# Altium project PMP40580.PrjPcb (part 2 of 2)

## Sheet PMP40580_LLC.SchDoc
size 431 x 279 mm; Date: Not shown in title block; ApprovedBy: Not shown in title block; CheckedBy: Not shown in title block; Author: Not shown in title block; CompanyName: Not shown in title block; DrawnBy: Oliver Pan; Engineer: Not shown in title block; Organization: Not shown in title block; Address1: Not shown in title block; Address2: Not shown in title block; Address3: Not shown in title block; Address4: Not shown in title block; DocumentNumber: 1; Revision: Use project parameter SCH_Rev; SheetNumber: 3; SheetTotal: 3; PageSetup: Record=PageOptions¦CenterHorizontal=True¦CenterVertical=True¦PrintScale=0.64¦XCorrection=1.00¦YCorrection=1.00¦PrintKind=1¦BorderSize=5000000¦LeftOffset=0¦BottomOffset=0¦Orientation=2¦PaperLength=1000¦PaperWidth=1000¦Scale=100¦PaperSource=15¦PrintQuality=-3¦MediaType=1¦DitherType=10¦PrintScaleMode=1¦PaperKind=Letter¦PaperIndex=1
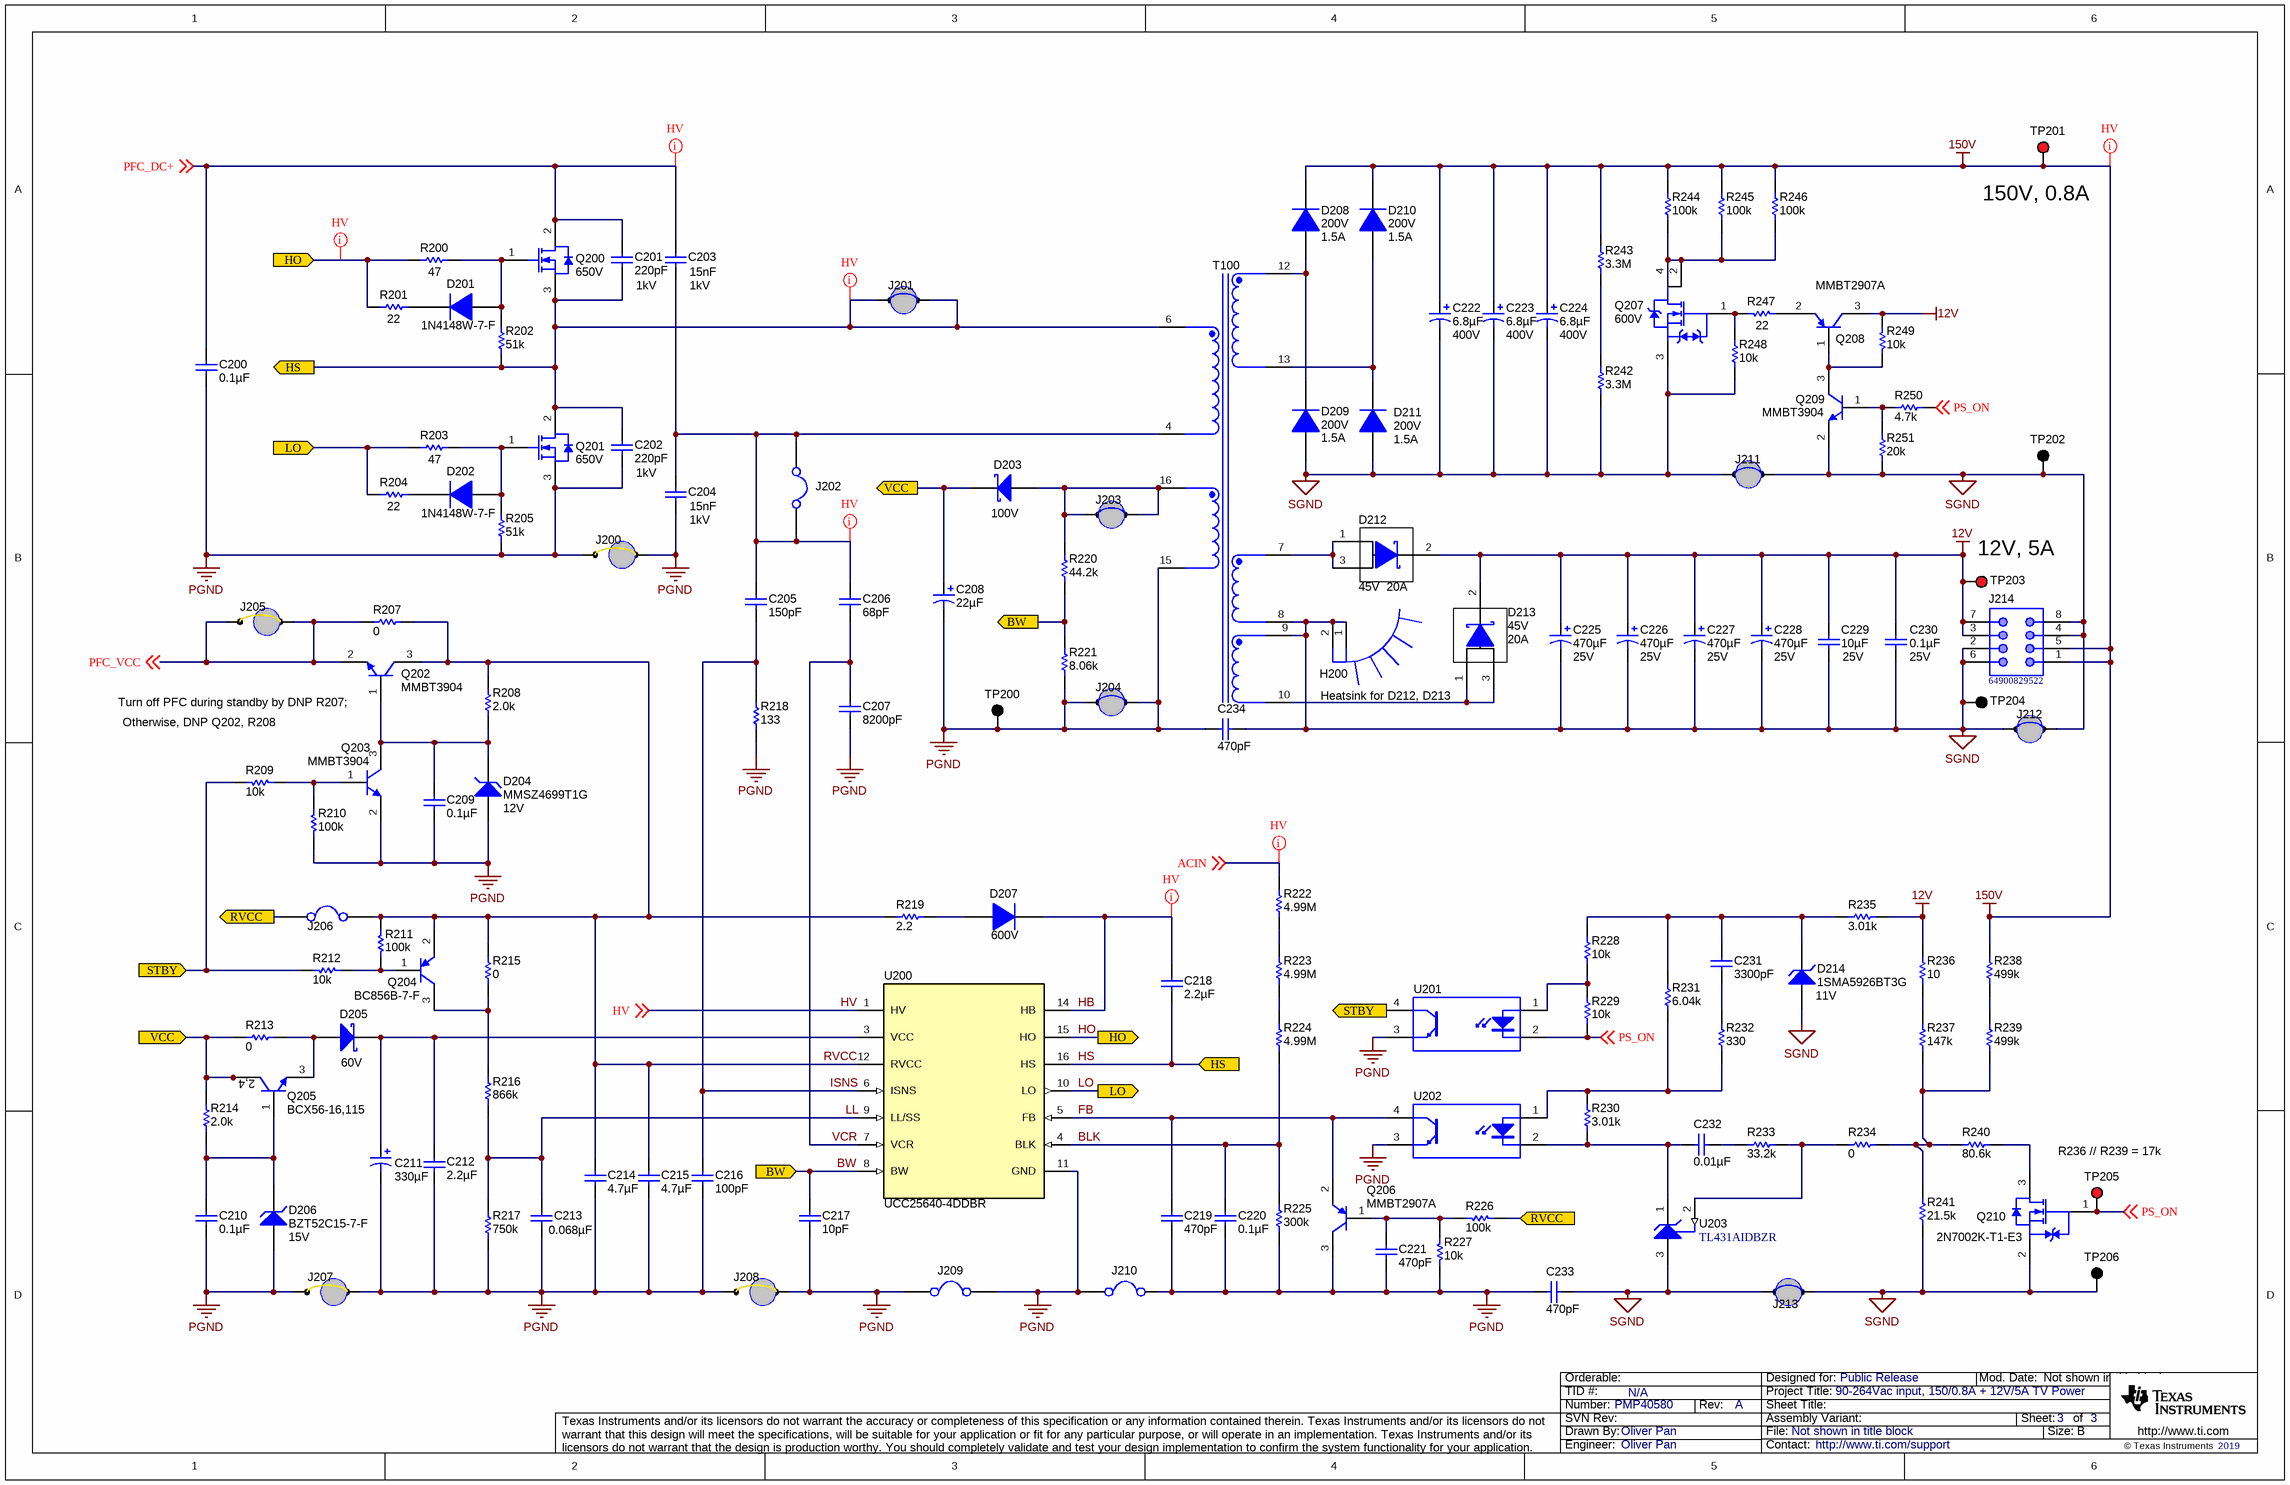
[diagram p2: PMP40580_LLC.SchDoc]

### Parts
C200  ValueDisplayed: 0.1µF  [1210_280]  (hidden comment: C1210C104KBRAC7800)
C201  ValueDisplayed: 220pF  Value2: 1kV  [CC45_850x500x1250]  (hidden comment: CC45SL3AD221JYNNA)
C202  ValueDisplayed: 220pF  Value2: 1kV  [CC45_850x500x1250]  (hidden comment: CC45SL3AD221JYNNA)
C203  value 15nF  Voltage Rating (DC): 1kV  [B32652_1800x700x1250]  (hidden comment: B32642B0153J)
C204  value 15nF  Voltage Rating (DC): 1kV  [B32652_1800x700x1250]  (hidden comment: B32642B0153J)
C205  ValueDisplayed: 150pF  [1206]  (hidden comment: GRM31A5C2J151JW01D)
C206  ValueDisplayed: 68pF  [1206]  (hidden comment: 12067A680JAT2A)
C207  ValueDisplayed: 8200pF  [1206]  (hidden comment: GRM3195C1H822JA01D)
C208  ValueDisplayed: 22µF  [Chemi-Con_500x1100]  (hidden comment: EKZE500ELL220ME11D)
C209  ValueDisplayed: 0.1µF  [0805_HV]  (hidden comment: 08055C104JAT2A)
C210  ValueDisplayed: 0.1µF  [0805_HV]  (hidden comment: 08055C104JAT2A)
C211  ValueDisplayed: 330µF  [VR_1000x1250]  (hidden comment: UVR1V331MPD)
C212  ValueDisplayed: 2.2µF  [1206_180]  (hidden comment: C3216X7S2A225K160AB)
C213  ValueDisplayed: 0.068µF  [0805_HV]  (hidden comment: C0805C683K1RACTU)
C214  ValueDisplayed: 4.7µF  [0805_HV]  (hidden comment: GRM21BR71E475KA73L)
C215  ValueDisplayed: 4.7µF  [0805_HV]  (hidden comment: GRM21BR71E475KA73L)
C216  ValueDisplayed: 100pF  [0805_HV]  (hidden comment: GRM2165C1H101JA01D)
C217  ValueDisplayed: 10pF  [0805_HV]  (hidden comment: C0805C100J5GACTU)
C218  ValueDisplayed: 2.2µF  [0805_HV]  (hidden comment: GRM219R71C225KE15)
C219  ValueDisplayed: 470pF  [0805_HV]  (hidden comment: GRM216R71E471KA01D)
C220  ValueDisplayed: 0.1µF  [0805_HV]  (hidden comment: C0805C104K3RACTU)
C221  ValueDisplayed: 470pF  [0805_HV]  (hidden comment: GRM216R71E471KA01D)
C222  ValueDisplayed: 6.8µF  Value2: 400V  [Chemi-Con_1000x1600]  (hidden comment: EKXG401ELL6R8MJ16S)
C223  ValueDisplayed: 6.8µF  Value2: 400V  [Chemi-Con_1000x1600]  (hidden comment: EKXG401ELL6R8MJ16S)
C224  ValueDisplayed: 6.8µF  Value2: 400V  [Chemi-Con_1000x1600]  (hidden comment: EKXG401ELL6R8MJ16S)
C225  ValueDisplayed: 470µF  Value2: 25V  [Chemi-Con_1000x1600]  (hidden comment: ELXZ250ELL471MJ16S)
C226  ValueDisplayed: 470µF  Value2: 25V  [Chemi-Con_1000x1600]  (hidden comment: ELXZ250ELL471MJ16S)
C227  ValueDisplayed: 470µF  Value2: 25V  [Chemi-Con_1000x1600]  (hidden comment: ELXZ250ELL471MJ16S)
C228  ValueDisplayed: 470µF  Value2: 25V  [Chemi-Con_1000x1600]  (hidden comment: ELXZ250ELL471MJ16S)
C229  ValueDisplayed: 10µF  Value2: 25V  [0805_HV]  (hidden comment: GRM21BC71E106KE11L)
C230  ValueDisplayed: 0.1µF  Value2: 25V  [0805_HV]  (hidden comment: GRM21BR71E104KA01L)
C231  ValueDisplayed: 3300pF  [0805_HV]  (hidden comment: 08055C332KAT2A)
C232  ValueDisplayed: 0.01µF  [0805_HV]  (hidden comment: C0805C103K1RACTU)
C233  ValueDisplayed: 470pF  [DE_800x1200x800]
C234  ValueDisplayed: 470pF  [DE_800x1200x800]
D201  1N4148W-7-F  [SOD-123]
D202  1N4148W-7-F  [SOD-123]
D203  value 100V  [SOD-123W]  (hidden comment: PMEG10020ELRX)
D204  MMSZ4699T1G  value 12V  [SOD-123]
D205  value 60V  [SOD-123F]  (hidden comment: PMEG6010CEH,115)
D206  BZT52C15-7-F  value 15V  [SOD-123]
D207  Vr_V: 600V  [SMAF]  (hidden comment: ES1JAF)
D208  value 200V  Value1: 1.5A  [DO-41_15mm]  (hidden comment: STTH1R02)
D209  value 200V  Value1: 1.5A  [DO-41_15mm]  (hidden comment: STTH1R02)
D210  value 200V  Value1: 1.5A  [DO-41_15mm]  (hidden comment: STTH1R02)
D211  value 200V  Value1: 1.5A  [DO-41_15mm]  (hidden comment: STTH1R02)
D212  value 45V  Value1: 20A  [TO-220FP_Horizontal_100mil_Standoff2300]  (hidden comment: STPS40L45CT)
D213  value 45V  Value1: 20A  [TO-220FP_Horizontal_100mil_Standoff2300]  (hidden comment: STPS40L45CT)
D214  1SMA5926BT3G  Vz_V: 11V  [SMA]
H200  SK44375SA  [SK-443-AL-75]  (value not drawn)
J200  923345-04-C  [3M_923345-04-C]  (value not drawn)
J201  923345-06-C  [CONN_923345-06-C]  (value not drawn)
J202  923345-08-C  [FP-923345-08-C_JUMPER2-MFG]  (value not drawn)
J203  923345-06-C  [CONN_923345-06-C]  (value not drawn)
J204  923345-06-C  [CONN_923345-06-C]  (value not drawn)
J205  923345-04-C  [3M_923345-04-C]  (value not drawn)
J206  923345-08-C  [FP-923345-08-C_JUMPER2-MFG]  (value not drawn)
J207  923345-04-C  [3M_923345-04-C]  (value not drawn)
J208  923345-04-C  [3M_923345-04-C]  (value not drawn)
J209  923345-08-C  [FP-923345-08-C_JUMPER2-MFG]  (value not drawn)
J210  923345-08-C  [FP-923345-08-C_JUMPER2-MFG]  (value not drawn)
J211  923345-06-C  [CONN_923345-06-C]  (value not drawn)
J212  923345-06-C  [CONN_923345-06-C]  (value not drawn)
J213  923345-06-C  [CONN_923345-06-C]  (value not drawn)
J214  64900829522  [64900829522]
Q200  value 650V  [TO-220FP_Horizontal_100mil_Standoff2300]  (hidden comment: IPA65R190CFD)
Q201  value 650V  [TO-220FP_Horizontal_100mil_Standoff2300]  (hidden comment: IPA65R190CFD)
Q202  MMBT3904  [SOT-23]
Q203  MMBT3904  [SOT-23]
Q204  BC856B-7-F  [SOT-23]
Q205  BCX56-16,115  [SOT-89-3]
Q206  MMBT2907A  [SOT-23]
Q207  value 600V  [SOT-223]  (hidden comment: STN1NK60Z)
Q208  MMBT2907A  [SOT-23]
Q209  MMBT3904  [SOT-23]
Q210  2N7002K-T1-E3  [SOT-23]
R200  ValueDisplayed: 47  [0805_HV]  (hidden comment: CRCW080547R0JNEA)
R201  ValueDisplayed: 22  [0805_HV]  (hidden comment: CRCW080522R0JNEA)
R202  ValueDisplayed: 51k  [0805_HV]  (hidden comment: CRCW080551K0JNEA)
R203  ValueDisplayed: 47  [0805_HV]  (hidden comment: CRCW080547R0JNEA)
R204  ValueDisplayed: 22  [0805_HV]  (hidden comment: CRCW080522R0JNEA)
R205  ValueDisplayed: 51k  [0805_HV]  (hidden comment: CRCW080551K0JNEA)
R207  ValueDisplayed: 0  [0805_HV]  (hidden comment: CRCW08050000Z0EA)
R208  ValueDisplayed: 2.0k  [0805_HV]  (hidden comment: CRCW08052K00JNEA)
R209  ValueDisplayed: 10k  [0805_HV]  (hidden comment: CRCW080510K0JNEA)
R210  ValueDisplayed: 100k  [0805_HV]  (hidden comment: CRCW0805100KJNEA)
R211  ValueDisplayed: 100k  [0805_HV]  (hidden comment: CRCW0805100KJNEA)
R212  ValueDisplayed: 10k  [0805_HV]  (hidden comment: CRCW080510K0JNEA)
R213  ValueDisplayed: 0  [0805_HV]  (hidden comment: CRCW08050000Z0EA)
R214  ValueDisplayed: 2.0k  [0805_HV]  (hidden comment: CRCW08052K00JNEA)
R215  ValueDisplayed: 0  [0805_HV]  (hidden comment: CRCW08050000Z0EA)
R216  ValueDisplayed: 866k  [0805_HV]  (hidden comment: CRCW0805866KFKEA)
R217  ValueDisplayed: 750k  [0805_HV]  (hidden comment: CRCW0805750KFKEA)
R218  ValueDisplayed: 133  [1206]  (hidden comment: CRCW1206133RFKEA)
R219  ValueDisplayed: 2.2  [0805_HV]  (hidden comment: CRCW08052R20JNEA)
R220  ValueDisplayed: 44.2k  [0805_HV]  (hidden comment: CRCW080544K2FKEA)
R221  ValueDisplayed: 8.06k  [0805_HV]  (hidden comment: CRCW08058K06FKEA)
R222  ValueDisplayed: 4.99M  [1206L]  (hidden comment: CRCW12064M99FKEA)
R223  ValueDisplayed: 4.99M  [1206L]  (hidden comment: CRCW12064M99FKEA)
R224  ValueDisplayed: 4.99M  [1206L]  (hidden comment: CRCW12064M99FKEA)
R225  ValueDisplayed: 300k  [0805_HV]  (hidden comment: CRCW0805300KJNEA)
R226  ValueDisplayed: 100k  [0805_HV]  (hidden comment: CRCW0805100KJNEA)
R227  ValueDisplayed: 10k  [0805_HV]  (hidden comment: CRCW080510K0JNEA)
R228  ValueDisplayed: 10k  [0805_HV]  (hidden comment: CRCW080510K0JNEA)
R229  ValueDisplayed: 10k  [0805_HV]  (hidden comment: CRCW080510K0JNEA)
R230  ValueDisplayed: 3.01k  [0805_HV]  (hidden comment: CRCW08053K01FKEA)
R231  ValueDisplayed: 6.04k  [0805_HV]  (hidden comment: CRCW08056K04FKEA)
R232  ValueDisplayed: 330  [0805_HV]  (hidden comment: CRCW0805330RJNEA)
R233  ValueDisplayed: 33.2k  [0805_HV]  (hidden comment: CRCW080533K2FKEA)
R234  ValueDisplayed: 0  [0805_HV]  (hidden comment: CRCW08050000Z0EA)
R235  ValueDisplayed: 3.01k  [0805_HV]  (hidden comment: CRCW08053K01FKEA)
R236  ValueDisplayed: 10  [0805_HV]  (hidden comment: CRCW080510R0JNEA)
R237  ValueDisplayed: 147k  [0805_HV]  (hidden comment: CRCW0805147KFKEA)
R238  ValueDisplayed: 499k  [0805_HV]  (hidden comment: CRCW0805499KFKEA)
R239  ValueDisplayed: 499k  [0805_HV]  (hidden comment: CRCW0805499KFKEA)
R240  ValueDisplayed: 80.6k  [0805_HV]  (hidden comment: CRCW080580K6FKEA)
R241  ValueDisplayed: 21.5k  [0805_HV]  (hidden comment: CRCW080521K5FKEA)
R242  ValueDisplayed: 3.3M  [0805_HV]  (hidden comment: ERJ-6GEYJ335V)
R243  ValueDisplayed: 3.3M  [0805_HV]  (hidden comment: ERJ-6GEYJ335V)
R244  ValueDisplayed: 100k  [PR02]  (hidden comment: PR02000201003JR500)
R245  ValueDisplayed: 100k  [PR02]  (hidden comment: PR02000201003JR500)
R246  ValueDisplayed: 100k  [PR02]  (hidden comment: PR02000201003JR500)
R247  ValueDisplayed: 22  [0805_HV]  (hidden comment: CRCW080522R0JNEA)
R248  ValueDisplayed: 10k  [0805_HV]  (hidden comment: CRCW080510K0JNEA)
R249  ValueDisplayed: 10k  [0805_HV]  (hidden comment: CRCW080510K0JNEA)
R250  ValueDisplayed: 4.7k  [0805_HV]  (hidden comment: CRCW08054K70JNEA)
R251  ValueDisplayed: 20k  [0805_HV]  (hidden comment: CRCW080520K0JNEA)
T100  BCK-50-722D  [EE49-8-20]  (value not drawn)
TP200  5011  [Keystone5011]  (value not drawn)
TP201  5010  [Keystone5010]  (value not drawn)
TP202  5011  [Keystone5011]  (value not drawn)
TP203  5010  [Keystone5010]  (value not drawn)
TP204  5011  [Keystone5011]  (value not drawn)
TP205  5010  [Keystone5010]  (value not drawn)
TP206  5011  [Keystone5011]  (value not drawn)
U200  PartNumber: UCC25640-4DDBR  [DDB0014A]  (hidden comment: UCC256440-4DDBR)
U201  VO618A  [DIP4-P-10.0-2.54]  (value not drawn)
U202  VO618A  [DIP4-P-10.0-2.54]  (value not drawn)
U203  TL431AIDBZR  [DBZ0003A_N]

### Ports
BW (in), BW (out), HO, HS, LO, RVCC, STBY (in), STBY (out), VCC (in), VCC (out)

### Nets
12V: C225.1(+) C226.1(+) C227.1(+) C228.1(+) C229.1 C230.1 D212.2(K) D213.2(K) J214.3 J214.7 Q208.3(C) R235.2 R236.2 R249.2 TP203.1
150V: C222.1(+) C223.1(+) C224.1(+) D208.1(K) D210.1(K) J214.1 J214.5 R238.2 R243.2 R244.2 R245.2 R246.2 TP201.1
PGND: C200.1 C202.1 C204.2 C207.2 C208.2(-) C209.2 C210.2 C211.2(-) C212.1 C213.2 C214.2 C215.2 C216.2 C217.2 C219.2 C220.2 C221.2 C233.1 C234.1 D204.2(A) D206.2(A) J200.1 J200.2 J204.1 J204.2 J207.1 J207.2 J208.1 J208.2 J209.1 J209.2 J210.1 J210.2 Q201.3(S) Q203.2(E) Q206.3(C) R205.1 R210.1 R217.1 R218.1 R221.1 R225.1 R227.2 T100.15 TP200.1 U200.11(GND) U201.3(E) U202.3(E)
SGND: C222.2(-) C223.2(-) C224.2(-) C225.2(-) C226.2(-) C227.2(-) C228.2(-) C229.2 C230.2 C233.2 C234.2 D209.2(A) D211.2(A) D214.2(A) H200.1 H200.2 J211.1 J211.2 J212.1 J212.2 J213.1 J213.2 J214.2 J214.4 J214.6 J214.8 Q207.3(S) Q209.2(E) Q210.2(S) R241.1 R242.1 R248.1 R251.1 T100.8 T100.9 TP202.1 TP204.1 TP206.1 U203.3(ANODE)
ACIN: R222.2 ; off-sheet ACIN
BLK: C220.1 R224.1 R225.2 U200.4(BLK)
BW: C217.1 R220.1 R221.2 U200.8(BW) ; port BW
FB: C219.1 Q206.2(E) U200.5(FB) U202.4(C)
HB: C218.1 D207.1(K) U200.14(HB)
HO: R200.1 R201.1 U200.15(HO) ; port HO
HS: C201.1 C202.2 C218.2 J201.1 J201.2 Q200.3(S) Q201.2(D) R202.1 T100.6 U200.16(HS) ; port HS
HV: U200.1(HV) ; off-sheet HV
ISNS: C205.2 C216.1 R218.2 U200.6(ISNS)
LL: C213.1 R216.1 R217.2 U200.9(LL/SS)
LO: R203.1 R204.1 U200.10(LO) ; port LO
PFC_DC+: C200.2 C201.2 C203.1 Q200.2(D) ; off-sheet PFC_DC+
PFC_VCC: J205.1 J205.2 Q202.2(E) R207.2 ; off-sheet PFC_VCC
PS_ON: Q210.1(G) R229.1 R250.2 TP205.1 U201.2(K) ; off-sheet PS_ON
RVCC: C214.1 C215.1 J206.1 Q202.3(C) Q204.2(E) R207.1 R208.2 R211.2 R215.2 R219.1 U200.12(RVCC)
RVCC: J206.2 R226.1 ; port RVCC  [a separate net that carries the same name]
STBY: R209.2 R212.2 U201.4(C) ; port STBY
VCC: C208.1(+) D203.1(K) Q205.2(C) Q205.4(C) R213.2 R214.2 ; port VCC
VCR: C206.2 C207.1 U200.7(VCR)
NetC203_2: C203.2 C204.1 C205.1 C206.1 J202.1 J202.2 T100.4
NetC209_1: C209.1 D204.1(K) Q202.1(B) Q203.3(C) R208.1
NetC210_1: C210.1 D206.1(K) Q205.1(B) R214.1
NetC211_1: C211.1(+) C212.2 D205.1(K) U200.3(VCC)
NetC221_1: C221.1 Q206.1(B) R226.2 R227.1
NetC231_1: C231.1 D214.1(K) R228.2 R231.2 R235.1
NetC231_2: C231.2 R232.2
NetC232_1: C232.1 R233.1
NetC232_2: C232.2 R230.2 U202.2(K) U203.1(CATHODE)
NetD201_1: D201.1(K) R201.2
NetD201_2: D201.2(A) Q200.1(G) R200.2 R202.2
NetD202_1: D202.1(K) R204.2
NetD202_2: D202.2(A) Q201.1(G) R203.2 R205.2
NetD203_2: D203.2(A) J203.1 J203.2 R220.2 T100.16
NetD205_2: D205.2(A) Q205.3(E) R213.1
NetD207_2: D207.2(A) R219.2
NetD208_2: D208.2(A) D209.1(K) T100.12
NetD210_2: D210.2(A) D211.1(K) T100.13
NetD212_1: D212.1(A) D212.3(A) T100.7
NetD213_1: D213.1(A) D213.3(A) T100.10
NetQ203_1: Q203.1(B) R209.1 R210.2
NetQ204_1: Q204.1(B) R211.1 R212.1
NetQ204_3: Q204.3(C) R215.1 R216.2
NetQ207_1: Q207.1(G) R247.2 R248.2
NetQ207_2: Q207.2(D) Q207.4(D) R244.1 R245.1 R246.1
NetQ208_1: Q208.1(B) Q209.3(C) R249.1
NetQ208_2: Q208.2(E) R247.1
NetQ209_1: Q209.1(B) R250.1 R251.2
NetQ210_3: Q210.3(D) R240.1
NetR222_1: R222.1 R223.2
NetR223_1: R223.1 R224.2
NetR228_1: R228.1 R229.2 U201.1(A)
NetR230_1: R230.1 R231.1 R232.1 U202.1(A)
NetR233_2: R233.2 R234.1 U203.2(REF)
NetR234_2: R234.2 R237.1 R239.1 R240.2 R241.2
NetR236_1: R236.1 R237.2
NetR238_1: R238.1 R239.2
NetR242_2: R242.2 R243.1

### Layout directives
rule Clearance Constraint [Clearance = 80mil]: ACIN, HB, HO, HS, NetC203_2, PFC_DC+
rule Clearance Constraint [Clearance = 50mil]: 150V

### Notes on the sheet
- (near TP201) 150V, 0.8A
- (near TP203) 12V, 5A
- (near Q202) Turn off PFC during standby by DNP R207;
- Heatsink for D212, D213
- Otherwise, DNP Q202, R208
- R236 // R239 = 17k

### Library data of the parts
C200 = C1210C104KBRAC7800: CAP, CERM, 0.1 µF, 630 V,+/- 10%, X7R, 1210; Manufacturer: Kemet; Polarized: N; CompType: Capacitor; Value: 0.1uF; U/M: EA; Cap_F: 0.0000001; Tolerance_%: 10; VDC_V: 630; Value2: 630V; TaMin_C: -55; TaMax_C: 125; Cap_Case: 1210; SizeAreaWB_mm2: 14.7; SizeArea_mm2: 8; SizeX_mm: 3.2; SizeY_mm: 2.5; SizeZ_mm: 2.8; AEC Category: Q200; Green_Lifecycle: Not Set; Green_REACh: Incomplete
C201 C202 = CC45SL3AD221JYNNA: CAP, CERM, 220 pF, 1000 V,+/- 5%, SL, D8.5xT5mm; Manufacturer: TDK; Polarized: N; CompType: Capacitor; Value: 220pF; U/M: EA; Cap_F: 0.00000000022; Tolerance_%: 5; VDC_V: 1000; TaMin_C: -25; TaMax_C: 125; Cap_Case: 8.5x5x12.5mm; SizeArea_mm2: 42.5; SizeAreaWB_mm2: 73.5; SizeX_mm: 8.5; SizeZ_mm: 12.5; AEC Category: Q200
C203 C204 = B32652A7153J000: CAP FILM 0.015UF 5% 1KVDC RADIAL; Manufacturer: TDK EPCOS; Dielectric Material: PP; Voltage Rating (AC): 600V
C205 = GRM31A5C2J151JW01D: CAP, CERM, 150 pF, 630 V,+/- 5%, C0G/NP0, 1206; Manufacturer: MuRata; Polarized: N; CompType: Capacitor; Value: 150pF; U/M: EA; Cap_F: 0.00000000015; Tolerance_%: 5; VDC_V: 630; Value2: 630V; TaMin_C: -55; TaMax_C: 125; SizeArea_mm2: 5.12; SizeAreaWB_mm2: 10.92; SizeX_mm: 3.2; SizeY_mm: 1.6; SizeZ_mm: 1.35; AEC Category: Q200
C206 = 12067A680JAT2A: CAP, CERM, 68 pF, 500 V,+/- 5%, C0G/NP0, 1206; Manufacturer: AVX; Polarized: N; CompType: Capacitor; Value: 68pF; U/M: EA; Cap_F: 0.000000000068; Tolerance_%: 5; VDC_V: 500; Value2: 500V; TaMin_C: -55; TaMax_C: 125; SizeArea_mm2: 5.12; SizeAreaWB_mm2: 10.92; SizeX_mm: 3.2; SizeY_mm: 1.6; SizeZ_mm: 1.35; AEC Category: Q200; Green_Lifecycle: Not Set; Green_REACh: Incomplete
C207 = GRM3195C1H822JA01D: CAP, CERM, 8200 pF, 50 V,+/- 5%, C0G/NP0, 1206; Manufacturer: MuRata; Polarized: N; CompType: Capacitor; Value: 8200pF; U/M: EA; Cap_F: 0.0000000082; Tolerance_%: 5; VDC_V: 50; Value2: 50V; TaMin_C: -55; TaMax_C: 125; SizeArea_mm2: 5.12; SizeAreaWB_mm2: 10.92; SizeX_mm: 3.2; SizeY_mm: 1.6; SizeZ_mm: 1.35; AEC Category: Q200
C208 = EKZE500ELL220ME11D: CAP, AL, 22 µF, 50 V, +/- 20%, TH; Manufacturer: Chemi-Con; Polarized: Y; CompType: Capacitor; Value: 22uF; U/M: EA; Cap_F: 0.000022; Tolerance_%: 20; VDC_V: 50; Value2: 50V; IRMS_A: 0.238; TaMin_C: -40; TaMax_C: 105; Cap_Case: 5x11; SizeAreaWB_mm2: 49; SizeArea_mm2: 25; SizeX_mm: 5; SizeZ_mm: 12.5; AEC Category: Q200; AEC Qualified: N
C209 C210 = 08055C104JAT2A: CAP, CERM, 0.1 µF, 50 V, +/- 5%, X7R, 0805; Manufacturer: AVX; Polarized: N; CompType: Capacitor; Value: 0.1uF; U/M: EA; Cap_F: 0.0000001; Tolerance_%: 5; ESR_ohm: 0.024; Value1: 0.024 ohm; VDC_V: 50; Value2: 50V; TaMin_C: -55; TaMax_C: 125; Cap_Case: 0805; SizeArea_mm2: 2.5; SizeAreaWB_mm2: 6.75; SizeX_mm: 2; SizeY_mm: 1.25; SizeZ_mm: 1.45; AEC Category: Q200
C211 = UVR1V331MPD: CAP, AL, 330 µF, 35 V, +/- 20%, TH; Manufacturer: Nichicon; Polarized: Y; CompType: Capacitor; Value: 330uF; U/M: EA; Cap_F: 0.00033; Tolerance_%: 20; VDC_V: 35; Value2: 35V; IRMS_A: 0.49; TaMin_C: -40; TaMax_C: 85; Cap_Case: 10x12.5; SizeAreaWB_mm2: 144; SizeArea_mm2: 100; SizeX_mm: 10; SizeZ_mm: 12.5; AEC Category: Q200; AEC Qualified: N; Green_Lifecycle: Active; Green_REACh: Passed
C212 = C3216X7S2A225K160AB: CAP, CERM, 2.2 µF, 100 V,+/- 10%, X7S, 1206; Manufacturer: TDK; Polarized: N; CompType: Capacitor; Value: 2.2uF; U/M: EA; Cap_F: 0.0000022; Tolerance_%: 10; ESR_ohm: 0.005718; Value1: 0.005718 ohm; VDC_V: 100; Value2: 100V; IRMS_A: 3.03632; TaMin_C: -55; TaMax_C: 125; Cap_Case: 1206; SizeArea_mm2: 5.12; SizeAreaWB_mm2: 10.92; SizeX_mm: 3.2; SizeY_mm: 1.6; SizeZ_mm: 1.8; AEC Category: Q200
C213 = C0805C683K1RACTU: CAP, CERM, 0.068 µF, 100 V,+/- 10%, X7R, 0805; Manufacturer: Kemet; Polarized: N; CompType: Capacitor; Value: 0.068uF; U/M: EA; Cap_F: 0.000000068; Tolerance_%: 10; ESR_ohm: 0.078; Value1: 0.078 ohm; VDC_V: 100; Value2: 100V; IRMS_A: 1.28; TaMin_C: -55; TaMax_C: 125; Cap_Case: 0805; SizeArea_mm2: 2.5; SizeAreaWB_mm2: 6.75; SizeX_mm: 2; SizeY_mm: 1.25; SizeZ_mm: 1.45; AEC Category: Q200; Green_Lifecycle: Not Set; Green_REACh: Incomplete
C214 C215 = GRM21BR71E475KA73L: CAP, CERM, 4.7 µF, 25 V,+/- 10%, X7R, 0805; Manufacturer: MuRata; Polarized: N; CompType: Capacitor; Value: 4.7uF; U/M: EA; Cap_F: 0.0000047; Tolerance_%: 10; VDC_V: 25; Value2: 25V; TaMin_C: -55; TaMax_C: 125; Cap_Case: 0805; SizeArea_mm2: 2.5; SizeAreaWB_mm2: 6.75; SizeX_mm: 2; SizeY_mm: 1.25; SizeZ_mm: 1.45; AEC Category: Q200
C216 = GRM2165C1H101JA01D: CAP, CERM, 100 pF, 50 V,+/- 5%, C0G/NP0, 0805; Manufacturer: MuRata; Polarized: N; CompType: Capacitor; Value: 100pF; U/M: EA; Cap_F: 0.0000000001; Tolerance_%: 5; VDC_V: 50; Value2: 50V; TaMin_C: -55; TaMax_C: 125; Cap_Case: 0805; SizeArea_mm2: 2.5; SizeAreaWB_mm2: 6.75; SizeX_mm: 2; SizeY_mm: 1.25; SizeZ_mm: 1.45; AEC Category: Q200; Green_Lifecycle: Active; Green_REACh: Passed
C217 = C0805C100J5GACTU: CAP, CERM, 10 pF, 50 V,+/- 5%, C0G/NP0, 0805; Manufacturer: Kemet; Polarized: N; CompType: Capacitor; Value: 10pF; U/M: EA; Cap_F: 0.00000000001; Tolerance_%: 5; ESR_ohm: 0.285; Value1: 0.285 ohm; VDC_V: 50; Value2: 50V; IRMS_A: 0.221; TaMin_C: -55; TaMax_C: 125; Cap_Case: 0805; SizeArea_mm2: 2.5; SizeAreaWB_mm2: 6.75; SizeX_mm: 2; SizeY_mm: 1.25; SizeZ_mm: 1.45; AEC Category: Q200; Green_Lifecycle: Not Set; Green_REACh: Incomplete
C218 = GRM219R71C225KE15: CAP, CERM, 2.2 µF, 16 V,+/- 10%, X7R, 0805; Manufacturer: MuRata; Polarized: N; CompType: Capacitor; Value: 2.2uF; U/M: EA; Cap_F: 0.0000022; Tolerance_%: 10; VDC_V: 16; Value2: 16V; TaMin_C: -55; TaMax_C: 125; Cap_Case: 0805; SizeArea_mm2: 2.5; SizeAreaWB_mm2: 6.75; SizeX_mm: 2; SizeY_mm: 1.25; SizeZ_mm: 1.45; AEC Category: Q200
C219 C221 = GRM216R71E471KA01D: CAP, CERM, 470 pF, 25 V,+/- 10%, X7R, 0805; Manufacturer: MuRata; Polarized: N; CompType: Capacitor; Value: 470pF; U/M: EA; Cap_F: 0.00000000047; Tolerance_%: 10; VDC_V: 25; Value2: 25V; TaMin_C: -55; TaMax_C: 125; Cap_Case: 0805; SizeArea_mm2: 2.5; SizeAreaWB_mm2: 6.75; SizeX_mm: 2; SizeY_mm: 1.25; SizeZ_mm: 1.45; AEC Category: Q200
C220 = C0805C104K3RACTU: CAP, CERM, 0.1 µF, 25 V,+/- 10%, X7R, 0805; Manufacturer: Kemet; Polarized: N; CompType: Capacitor; Value: 0.1uF; U/M: EA; Cap_F: 0.0000001; Tolerance_%: 10; ESR_ohm: 0.064; Value1: 0.064 ohm; VDC_V: 25; Value2: 25V; IRMS_A: 1.64; TaMin_C: -55; TaMax_C: 125; Cap_Case: 0805; SizeArea_mm2: 2.5; SizeAreaWB_mm2: 6.75; SizeX_mm: 2; SizeY_mm: 1.25; SizeZ_mm: 1.45; AEC Category: Q200; Green_Lifecycle: Active; Green_REACh: Passed
C222-C224 = EKXG401ELL6R8MJ16S: CAP, AL, 6.8 µF, 400 V, +/- 20%, TH; Manufacturer: Chemi-Con; Value: 6.8uF; VDC_V: 400; Tolerance_%: 20; Polarized: Y; CompType: Capacitor; U/M: EA; Cap_F: 0.0000068; IRMS_A: 0.11; TaMin_C: -40; TaMax_C: 105; Cap_Case: 10x16mm; SizeAreaWB_mm2: 144; SizeArea_mm2: 100; SizeX_mm: 10; SizeZ_mm: 17.5; AEC Category: Q200; AEC Qualified: N; Green_Lifecycle: Not Set; Green_REACh: Incomplete
C225-C228 = ELXZ250ELL471MJ16S: CAP, AL, 470 µF, 25 V, +/- 20%, AEC-Q200 Grade 2, TH; Manufacturer: Chemi-Con; Polarized: Y; CompType: Capacitor; Value: 470uF; U/M: EA; Cap_F: 0.00047; Tolerance_%: 20; VDC_V: 25; IRMS_A: 1.05; TaMin_C: -55; TaMax_C: 105; Cap_Case: 10x16mm; SizeAreaWB_mm2: 144; SizeArea_mm2: 100; SizeX_mm: 10; SizeZ_mm: 17.5; AEC Category: Q200; AEC Grade: 2
C229 = GRM21BC71E106KE11L: CAP, CERM, 10 µF, 25 V,+/- 10%, X7S, 0805; Manufacturer: MuRata; Polarized: N; CompType: Capacitor; Value: 10uF; U/M: EA; Cap_F: 0.00001; Tolerance_%: 10; VDC_V: 25; TaMin_C: -55; TaMax_C: 125; Cap_Case: 0805; SizeArea_mm2: 2.5; SizeAreaWB_mm2: 6.75; SizeX_mm: 2; SizeY_mm: 1.25; SizeZ_mm: 1.45; AEC Category: Q200
C230 = GRM21BR71E104KA01L: CAP, CERM, 0.1 µF, 25 V,+/- 10%, X7R, 0805; Manufacturer: MuRata; Polarized: N; CompType: Capacitor; Value: 0.1uF; U/M: EA; Cap_F: 0.0000001; Tolerance_%: 10; VDC_V: 25; TaMin_C: -55; TaMax_C: 125; Cap_Case: 0805; SizeArea_mm2: 2.5; SizeAreaWB_mm2: 6.75; SizeX_mm: 2; SizeY_mm: 1.25; SizeZ_mm: 1.45; AEC Category: Q200; Green_Lifecycle: Active; Green_REACh: Passed
C231 = 08055C332KAT2A: CAP, CERM, 3300 pF, 50 V,+/- 10%, X7R, 0805; Manufacturer: AVX; Polarized: N; CompType: Capacitor; Value: 3300pF; U/M: EA; Cap_F: 0.0000000033; Tolerance_%: 10; ESR_ohm: 0.145; Value1: 0.145 ohm; VDC_V: 50; Value2: 50V; TaMin_C: -55; TaMax_C: 125; Cap_Case: 0805; SizeArea_mm2: 2.5; SizeAreaWB_mm2: 6.75; SizeX_mm: 2; SizeY_mm: 1.25; SizeZ_mm: 1.45; AEC Category: Q200; Green_Lifecycle: Not Set; Green_REACh: Incomplete
C232 = C0805C103K1RACTU: CAP, CERM, 0.01 µF, 100 V,+/- 10%, X7R, 0805; Manufacturer: Kemet; Polarized: N; CompType: Capacitor; Value: 0.01uF; U/M: EA; Cap_F: 0.00000001; Tolerance_%: 10; ESR_ohm: 1.739; Value1: 1.739 ohm; VDC_V: 100; Value2: 100V; IRMS_A: 0.411; TaMin_C: -55; TaMax_C: 125; Cap_Case: 0805; SizeArea_mm2: 2.5; SizeAreaWB_mm2: 6.75; SizeX_mm: 2; SizeY_mm: 1.25; SizeZ_mm: 1.45; AEC Category: Q200; Green_Lifecycle: Active; Green_REACh: Passed
C233 C234 = DE1E3KX102MA5BA01: CAP, CERM, 470 pF, 250 V, +/- 20%, E, Disc, 8x12mm; Manufacturer: MuRata; Polarized: N; CompType: Capacitor; Value: 1000pF; U/M: EA; Cap_F: 0.000000001; Tolerance_%: 20; Value1: Unknown; VDC_V: 250; Value2: 250V; TaMin_C: -25; TaMax_C: 85; SizeArea_mm2: 64; SizeAreaWB_mm2: 100; SizeX_mm: 8; SizeZ_mm: 12; AEC Category: Q200
D201 D202 = 1N4148W-7-F: Diode, Ultrafast, 100 V, 0.15 A, SOD-123; Manufacturer: Diodes Inc.; U/M: EA; Vf_V: 1.25; Value: 100V; Value1: 0.15A; Value2: 1.25V; Io_A: 0.15; Vr_V: 100; TJmax_C: 150; SizeAreaWB_mm2: 13.095; SizeArea_mm2: 6.545; SizeX_mm: 3.85; SizeY_mm: 1.7; SizeZ_mm: 1.35; AEC Category: Q101
D203 = PMEG10020ELRX: Diode, Schottky, 100 V, 2 A, AEC-Q101, SOD-123W; Manufacturer: Nexperia; U/M: EA; Vf_V: 0.83; Value1: 2A; Value2: 0.83V; Io_A: 2; Vr_V: 100; TJmax_C: 175; SizeAreaWB_mm2: 12.15; SizeArea_mm2: 5.95; SizeX_mm: 3.5; SizeY_mm: 1.7; SizeZ_mm: 1; AEC Category: Q101; AEC Qualified: Y
D204 = MMSZ4699T1G: Diode, Zener, 12 V, 500 mW, SOD-123; Manufacturer: ON Semiconductor; SymbolCreator: a0412235; U/M: EA; Power_W: 0.5; Vz_V: 12; Value1: 0.5W; RJA_CperW: 340; SizeAreaWB_mm2: 13.095; SizeArea_mm2: 6.545; SizeX_mm: 3.85; SizeY_mm: 1.7; SizeZ_mm: 1.35; AEC Category: Q101
D205 = PMEG6010CEH,115: Diode, Schottky, 60 V, 1 A, SOD-123F; Manufacturer: Nexperia; U/M: EA; Vf_V: 0.57; Value1: 1A; Value2: 0.57V; Io_A: 1; Vr_V: 60; TJmax_C: 150; SizeAreaWB_mm2: 11.7; SizeArea_mm2: 5.6; SizeX_mm: 3.5; SizeY_mm: 1.6; SizeZ_mm: 1.1; AEC Category: Q101; Green_Lifecycle: Not Set; Green_REACh: Incomplete
D206 = BZT52C15-7-F: Diode, Zener, 15 V, 370 mW, AEC-Q101, SOD-123; Manufacturer: Diodes Inc.; SymbolCreator: a0412235; U/M: EA; Power_W: 0.37; Vz_V: 15; Value1: 0.37W; RJA_CperW: 338; SizeAreaWB_mm2: 13.095; SizeArea_mm2: 6.545; SizeX_mm: 3.85; SizeY_mm: 1.7; SizeZ_mm: 1.35; AEC Category: Q101; AEC Qualified: Y
D207 = CMP-0029162-1: Diode, Ultrafast, 600 V, 1 A, AEC-Q101, SMAF; Manufacturer: Fairchild Semiconductor; Io_A: 1A; Green_Lifecycle: Not Set; SizeAreaWB_mm2: 19.95; Green_REACh: Incomplete; TJmax_C: 150°C; U/M: EA; Value: 600V; SizeZ_mm: 1; SizeX_mm: 4.7; SizeY_mm: 2.5; Vf_V: 1.7V; SizeArea_mm2: 11.75; AEC Qualified: Y; AEC Category: Q101
D208-D211 = STTH1R02: Diode, Ultrafast, 200 V, 1.5 A, TH; Manufacturer: STMicroelectronics; U/M: EA; Vf_V: 1; Value2: 1V; Io_A: 1.5; Vr_V: 200; TJmax_C: 175; SizeAreaWB_mm2: 43.424; SizeArea_mm2: 19.584; SizeX_mm: 7.2; SizeY_mm: 2.72; SizeZ_mm: 23.4; AEC Category: Q101; AEC Qualified: N; Green_Lifecycle: Not Set; Green_REACh: Incomplete
D212 D213 = STPS40L45CT: Diode, Schottky, 45 V, 20 A, TH; Manufacturer: STMicroelectronics; U/M: EA; Vf_V: 0.49; Value2: 0.49V; Io_A: 20; Vr_V: 45; TJmax_C: 150; RJC_CperW: 0.8; SizeAreaWB_mm2: 79.3; SizeArea_mm2: 45.9; SizeX_mm: 10.2; SizeY_mm: 4.5; SizeZ_mm: 19.4; AEC Category: Q101; Green_Lifecycle: Active; Green_REACh: Passed
D214 = CMP-0005522-2: Diode, Zener, 11 V, 1.5 W, SMA; Manufacturer: ON Semiconductor; Power_W: 1.5W; SizeAreaWB_mm2: 37.3428; RJA_CperW: 250; U/M: EA; Value: 11V; SizeZ_mm: 2.87; SizeX_mm: 5.59; SizeY_mm: 2.92; SizeArea_mm2: 16.3228; AEC Category: Q101
H200 = HeatSink_2840x500x600_PQFP64-PBH: Extruded Heatsink, 75mm, CUSTOM; Manufacturer: Texas Instruments; SymbolCreator: a0799628
J200 J205 J207 J208 = 923345-04-C: Jumper Wire, 400 mil Spacing, Yellow, Pkg of 200; Manufacturer: 3M; SymbolCreator: Altium; Green_Lifecycle: Active; Green_REACh: Passed
J201 J203 J204 J211-J213 = 923345-06-C: Jumper Wire, 600mil spacing, Blue, pkg of 150, TH; Manufacturer: 3M; SymbolCreator: a0412235; Green_Lifecycle: Active; Green_REACh: Passed
J202 J206 J209 J210 = CMP-0086939-1: Manufacturer: 3M; ContactFinish: Tin
J214 = 64900829522: THT Male Header WR-MPC4, Right Angled, Dual Row, pitch 4.2 mm, 8 pins; Pitch: 4.2 mm; Working Voltage: 600 VAC; Contact Resistance: 10 mOhm; Pin Number: 8
Q200 Q201 = IPA65R190CFD: MOSFET, N-CH, 650 V, 17.5 A, TO-220FP; Manufacturer: Infineon Technologies; Alternate Manufacturer: None; U/M: EA; ChType: N; VdsMax_V: 650; Value1: ? ohm; Value2: 68 nC; QgTyp_nC: 68; Vgs_V: 20; IdsMax_A: 17.5; SizeAreaWB_mm2: 79.3; SizeArea_mm2: 45.9; SizeX_mm: 10.2; SizeY_mm: 4.5; AEC Category: Q101
Q202 Q203 Q209 = MMBT3904, Fairchild Semiconductor: Transistor, NPN, 40 V, 0.2 A, SOT-23; CompType: BJT; PNP: 0; NPN: 1; Vceo_V: 40; Vcesat1_V: 0.2; Value: 40 V; Value1: 0.2 A; HfeMax: 300; TaMin_C: -55; TaMax_C: 150; SizeAreaWB_mm2: 14; SizeArea_mm2: 7.5; SizeX_mm: 2.5; SizeY_mm: 3; SizeZ_mm: 1.1; U/M: EA; AEC Category: Q101
Q204 = BC856B-7-F, Diodes Inc.: Transistor, PNP, 65 V, 0.1 A, SOT-23; CompType: BJT; PNP: 1; NPN: 0; Vceo_V: 65; Vcesat1_V: 0.075; Value: 65 V; IcRated_A: 0.1; Value1: 0.1 A; HfeMax: 330; TaMin_C: -65; TaMax_C: 150; SizeAreaWB_mm2: 14; SizeArea_mm2: 7.5; SizeX_mm: 2.5; SizeY_mm: 3; SizeZ_mm: 1.1; U/M: EA; AEC Category: Q101
Q205 = BCX56-16,115, Nexperia: Transistor, NPN, 80 V, 1 A, AEC-Q101, SOT-89; SymbolCreator: a0412235; PNP: 0; NPN: 1; Vceo_V: 80; Vcesat1_V: 0.5; Value: 80 V; Value1: 1 A; HfeMax: 250; TaMin_C: -55; TaMax_C: 150; SizeAreaWB_mm2: 28.05; SizeArea_mm2: 18.45; SizeX_mm: 4.1; SizeY_mm: 4.5; SizeZ_mm: 1.5; CompType: BJT; U/M: EA; AEC Category: Q101; AEC Qualified: Y
Q206 Q208 = MMBT2907A, Fairchild Semiconductor: Transistor, PNP, 60 V, 0.8 A, SOT-23; CompType: BJT; PNP: 1; NPN: 0; Vceo_V: 60; Vcesat1_V: 1.6; Value: 60 V; IcRated_A: 0.8; Value1: 0.8 A; HfeMax: 300; TaMin_C: -55; TaMax_C: 150; SizeAreaWB_mm2: 14; SizeArea_mm2: 7.5; SizeX_mm: 2.5; SizeY_mm: 3; SizeZ_mm: 1.1; U/M: EA; AEC Category: Q101
Q207 = STN1NK60Z: MOSFET, N-CH, 600 V, 0.3 A, SOT-223; Manufacturer: STMicroelectronics; Alternate Manufacturer: None; SymbolCreator: a0411947; U/M: EA; ChType: N; VdsMax_V: 600; Value1: ? ohm; Value2: 4.9 nC; QgTyp_nC: 4.9; Vgs_V: 30; IdsMax_A: 0.3; SizeAreaWB_mm2: 76.5; SizeArea_mm2: 45.5; SizeX_mm: 6.5; SizeY_mm: 7; SizeZ_mm: 1.6; AEC Category: Q101
Q210 = 2N7002K-T1-E3: MOSFET, N-CH, 60 V, 0.3 A, SOT-23; Manufacturer: Vishay-Siliconix; Alternate Manufacturer: None; SymbolCreator: a0411947; U/M: EA; ChType: N; Value: 60V; VdsMax_V: 60; Value1: 4 ohm; Rdson45_ohm: 4; Value2: 0.4 nC; QgTyp_nC: 0.4; Vgs_V: 20; IdsMax_A: 0.3; SizeAreaWB_mm2: 14; SizeArea_mm2: 7.5; SizeX_mm: 2.5; SizeY_mm: 3; SizeZ_mm: 1.1; AEC Category: Q101; Green_Lifecycle: Active; Green_REACh: Passed
R200 R203 = CRCW080547R0JNEA: RES, 47, 5%, 0.125 W, 0805; Manufacturer: Vishay-Dale; CompType: Resistor; Value: 47; Value_Code: 47R0; Tolerance_%: 5; Power_W: 0.125; Value2: 0.125W; VDC_V: 150; TempCo: 200 ppm/C; SizeArea_mm2: 2.5; SizeX_mm: 2; SizeY_mm: 1.25; SizeZ_mm: 1.45; EIA_Code: E24; U/M: EA; AEC Category: Q200
R201 R204 R247 = CRCW080522R0JNEA: RES, 22, 5%, 0.125 W, 0805; Manufacturer: Vishay-Dale; CompType: Resistor; Value: 22; Value_Code: 22R0; Tolerance_%: 5; Power_W: 0.125; Value2: 0.125W; VDC_V: 150; TempCo: 200 ppm/C; SizeArea_mm2: 2.5; SizeX_mm: 2; SizeY_mm: 1.25; SizeZ_mm: 1.45; EIA_Code: E24; U/M: EA; AEC Category: Q200; Green_Lifecycle: Active; Green_REACh: Passed
R202 R205 = CRCW080551K0JNEA: RES, 51 k, 5%, 0.125 W, 0805; Manufacturer: Vishay-Dale; CompType: Resistor; Value: 51k; Res_ohm: 51000; Value_Code: 51k0; Tolerance_%: 5; Power_W: 0.125; Value2: 0.125W; VDC_V: 150; TempCo: 200 ppm/C; SizeArea_mm2: 2.5; SizeX_mm: 2; SizeY_mm: 1.25; SizeZ_mm: 1.45; EIA_Code: E24; U/M: EA; AEC Category: Q200
R207 R213 R215 R234 = CRCW08050000Z0EA: RES, 0, 5%, 0.125 W, 0805; Manufacturer: Vishay-Dale; CompType: Resistor; Value: 0; Value_Code: 0000; Tolerance_%: 5; Power_W: 0.125; Value2: 0.125W; VDC_V: 150; TempCo: 200 ppm/C; SizeArea_mm2: 2.5; SizeX_mm: 2; SizeY_mm: 1.25; SizeZ_mm: 1.45; EIA_Code: E24; U/M: EA; AEC Category: Q200; Green_Lifecycle: Active; Green_REACh: Passed
R208 R214 = CRCW08052K00JNEA: RES, 2.0 k, 5%, 0.125 W, 0805; Manufacturer: Vishay-Dale; CompType: Resistor; Value: 2.0k; Res_ohm: 2000; Value_Code: 2k00; Tolerance_%: 5; Power_W: 0.125; Value2: 0.125W; VDC_V: 150; TempCo: 200 ppm/C; SizeArea_mm2: 2.5; SizeX_mm: 2; SizeY_mm: 1.25; SizeZ_mm: 1.45; EIA_Code: E24; U/M: EA; AEC Category: Q200; Green_Lifecycle: Active; Green_REACh: Passed
R209 R212 R227-R229 R248 R249 = CRCW080510K0JNEA: RES, 10 k, 5%, 0.125 W, 0805; Manufacturer: Vishay-Dale; CompType: Resistor; Value: 10k; Res_ohm: 10000; Value_Code: 10k0; Tolerance_%: 5; Power_W: 0.125; Value2: 0.125W; VDC_V: 150; TempCo: 200 ppm/C; SizeArea_mm2: 2.5; SizeX_mm: 2; SizeY_mm: 1.25; SizeZ_mm: 1.45; EIA_Code: E24; U/M: EA; AEC Category: Q200; Green_Lifecycle: Active; Green_REACh: Passed
R210 R211 R226 = CRCW0805100KJNEA: RES, 100 k, 5%, 0.125 W, 0805; Manufacturer: Vishay-Dale; CompType: Resistor; Value: 100k; Res_ohm: 100000; Tolerance_%: 5; Power_W: 0.125; Value2: 0.125W; VDC_V: 150; TempCo: 200 ppm/C; SizeArea_mm2: 2.5; SizeX_mm: 2; SizeY_mm: 1.25; SizeZ_mm: 1.45; EIA_Code: E24; U/M: EA; AEC Category: Q200; Green_Lifecycle: Active; Green_REACh: Passed
R216 = CRCW0805866KFKEA: RES, 866 k, 1%, 0.125 W, 0805; Manufacturer: Vishay-Dale; CompType: Resistor; Value: 866k; Res_ohm: 866000; Tolerance_%: 1; Power_W: 0.125; Value2: 0.125W; VDC_V: 150; TempCo: 100 ppm/C; SizeArea_mm2: 2.5; SizeX_mm: 2; SizeY_mm: 1.25; SizeZ_mm: 1.45; EIA_Code: E96; U/M: EA; AEC Category: Q200
R217 = CRCW0805750KFKEA: RES, 750 k, 1%, 0.125 W, 0805; Manufacturer: Vishay-Dale; CompType: Resistor; Value: 750k; Res_ohm: 750000; Tolerance_%: 1; Power_W: 0.125; Value2: 0.125W; VDC_V: 150; TempCo: 100 ppm/C; SizeArea_mm2: 2.5; SizeX_mm: 2; SizeY_mm: 1.25; SizeZ_mm: 1.45; EIA_Code: E96; U/M: EA; AEC Category: Q200; Green_Lifecycle: Active; Green_REACh: Passed
R218 = CRCW1206133RFKEA: RES, 133, 1%, 0.25 W, 1206; Manufacturer: Vishay-Dale; CompType: Resistor; Value: 133; Value_Code: 133R; Tolerance_%: 1; Power_W: 0.25; Value2: 0.25W; VDC_V: 200; TempCo: 100 ppm/C; SizeArea_mm2: 5.12; SizeX_mm: 3.2; SizeY_mm: 1.6; SizeZ_mm: 1.35; EIA_Code: E96; U/M: EA; AEC Category: Q200
R219 = CRCW08052R20JNEA: RES, 2.2, 5%, 0.125 W, 0805; Manufacturer: Vishay-Dale; CompType: Resistor; Value: 2.2; Value_Code: 2R20; Tolerance_%: 5; Power_W: 0.125; Value2: 0.125W; VDC_V: 150; TempCo: 200 ppm/C; SizeArea_mm2: 2.5; SizeX_mm: 2; SizeY_mm: 1.25; SizeZ_mm: 1.45; EIA_Code: E24; U/M: EA; AEC Category: Q200; Green_Lifecycle: Active; Green_REACh: Passed
R220 = CRCW080544K2FKEA: RES, 44.2 k, 1%, 0.125 W, 0805; Manufacturer: Vishay-Dale; CompType: Resistor; Value: 44.2k; Res_ohm: 44200; Value_Code: 44k2; Tolerance_%: 1; Power_W: 0.125; Value2: 0.125W; VDC_V: 150; TempCo: 100 ppm/C; SizeArea_mm2: 2.5; SizeX_mm: 2; SizeY_mm: 1.25; SizeZ_mm: 1.45; EIA_Code: E96; U/M: EA; AEC Category: Q200
R221 = CRCW08058K06FKEA: RES, 8.06 k, 1%, 0.125 W, 0805; Manufacturer: Vishay-Dale; CompType: Resistor; Value: 8.06k; Res_ohm: 8060; Value_Code: 8k06; Tolerance_%: 1; Power_W: 0.125; Value2: 0.125W; VDC_V: 150; TempCo: 100 ppm/C; SizeArea_mm2: 2.5; SizeX_mm: 2; SizeY_mm: 1.25; SizeZ_mm: 1.45; EIA_Code: E96; U/M: EA; AEC Category: Q200; Green_Lifecycle: Active; Green_REACh: Passed
R222-R224 = CMP-0017039-3: RES, 4.99 M, 1%, 0.25 W, AEC-Q200 Grade 0, 1206; Manufacturer: Vishay-Dale; Power_W: 250mW; TempCo: 100 ppm/C; Value_Code: 4M99; Value: 4.99Meg; EIA_Code: E96; SizeX_mm: 3.2; SizeY_mm: 1.6; SizeZ_mm: 1.35; Value2: 0.25W; SizeArea_mm2: 5.12; CompType: Resistor; AEC Qualified: Y; VDC_V: 200V; AEC Category: Q200; AEC Grade: 0
R225 = CRCW0805300KJNEA: RES, 300 k, 5%, 0.125 W, 0805; Manufacturer: Vishay-Dale; CompType: Resistor; Value: 300k; Res_ohm: 300000; Tolerance_%: 5; Power_W: 0.125; Value2: 0.125W; VDC_V: 150; TempCo: 200 ppm/C; SizeArea_mm2: 2.5; SizeX_mm: 2; SizeY_mm: 1.25; SizeZ_mm: 1.45; EIA_Code: E24; U/M: EA; AEC Category: Q200
R230 R235 = CRCW08053K01FKEA: RES, 3.01 k, 1%, 0.125 W, 0805; Manufacturer: Vishay-Dale; CompType: Resistor; Value: 3.01k; Res_ohm: 3010; Value_Code: 3k01; Tolerance_%: 1; Power_W: 0.125; Value2: 0.125W; VDC_V: 150; TempCo: 100 ppm/C; SizeArea_mm2: 2.5; SizeX_mm: 2; SizeY_mm: 1.25; SizeZ_mm: 1.45; EIA_Code: E96; U/M: EA; AEC Category: Q200; Green_Lifecycle: Active; Green_REACh: Passed
R231 = CRCW08056K04FKEA: RES, 6.04 k, 1%, 0.125 W, 0805; Manufacturer: Vishay-Dale; CompType: Resistor; Value: 6.04k; Res_ohm: 6040; Value_Code: 6k04; Tolerance_%: 1; Power_W: 0.125; Value2: 0.125W; VDC_V: 150; TempCo: 100 ppm/C; SizeArea_mm2: 2.5; SizeX_mm: 2; SizeY_mm: 1.25; SizeZ_mm: 1.45; EIA_Code: E96; U/M: EA; AEC Category: Q200
R232 = CRCW0805330RJNEA: RES, 330, 5%, 0.125 W, 0805; Manufacturer: Vishay-Dale; CompType: Resistor; Value: 330; Value_Code: 330R; Tolerance_%: 5; Power_W: 0.125; Value2: 0.125W; VDC_V: 150; TempCo: 200 ppm/C; SizeArea_mm2: 2.5; SizeX_mm: 2; SizeY_mm: 1.25; SizeZ_mm: 1.45; EIA_Code: E24; U/M: EA; AEC Category: Q200
R233 = CRCW080533K2FKEA: RES, 33.2 k, 1%, 0.125 W, 0805; Manufacturer: Vishay-Dale; CompType: Resistor; Value: 33.2k; Res_ohm: 33200; Value_Code: 33k2; Tolerance_%: 1; Power_W: 0.125; Value2: 0.125W; VDC_V: 150; TempCo: 100 ppm/C; SizeArea_mm2: 2.5; SizeX_mm: 2; SizeY_mm: 1.25; SizeZ_mm: 1.45; EIA_Code: E96; U/M: EA; AEC Category: Q200; Green_Lifecycle: Active; Green_REACh: Passed
R236 = CRCW080510R0JNEA: RES, 10, 5%, 0.125 W, 0805; Manufacturer: Vishay-Dale; CompType: Resistor; Value: 10; Value_Code: 10R0; Tolerance_%: 5; Power_W: 0.125; Value2: 0.125W; VDC_V: 150; TempCo: 200 ppm/C; SizeArea_mm2: 2.5; SizeX_mm: 2; SizeY_mm: 1.25; SizeZ_mm: 1.45; EIA_Code: E24; U/M: EA; AEC Category: Q200; Green_Lifecycle: Active; Green_REACh: Passed
R237 = CRCW0805147KFKEA: RES, 147 k, 1%, 0.125 W, 0805; Manufacturer: Vishay-Dale; CompType: Resistor; Value: 147k; Res_ohm: 147000; Tolerance_%: 1; Power_W: 0.125; Value2: 0.125W; VDC_V: 150; TempCo: 100 ppm/C; SizeArea_mm2: 2.5; SizeX_mm: 2; SizeY_mm: 1.25; SizeZ_mm: 1.45; EIA_Code: E96; U/M: EA; AEC Category: Q200
R238 R239 = CRCW0805499KFKEA: RES, 499 k, 1%, 0.125 W, 0805; Manufacturer: Vishay-Dale; CompType: Resistor; Value: 499k; Res_ohm: 499000; Tolerance_%: 1; Power_W: 0.125; Value2: 0.125W; VDC_V: 150; TempCo: 100 ppm/C; SizeArea_mm2: 2.5; SizeX_mm: 2; SizeY_mm: 1.25; SizeZ_mm: 1.45; EIA_Code: E96; U/M: EA; AEC Category: Q200; Green_Lifecycle: Active; Green_REACh: Passed
R240 = CRCW080580K6FKEA: RES, 80.6 k, 1%, 0.125 W, 0805; Manufacturer: Vishay-Dale; CompType: Resistor; Value: 80.6k; Res_ohm: 80600; Value_Code: 80k6; Tolerance_%: 1; Power_W: 0.125; Value2: 0.125W; VDC_V: 150; TempCo: 100 ppm/C; SizeArea_mm2: 2.5; SizeX_mm: 2; SizeY_mm: 1.25; SizeZ_mm: 1.45; EIA_Code: E96; U/M: EA; AEC Category: Q200; Green_Lifecycle: Active; Green_REACh: Passed
R241 = CRCW080521K5FKEA: RES, 21.5 k, 1%, 0.125 W, 0805; Manufacturer: Vishay-Dale; CompType: Resistor; Value: 21.5k; Res_ohm: 21500; Value_Code: 21k5; Tolerance_%: 1; Power_W: 0.125; Value2: 0.125W; VDC_V: 150; TempCo: 100 ppm/C; SizeArea_mm2: 2.5; SizeX_mm: 2; SizeY_mm: 1.25; SizeZ_mm: 1.45; EIA_Code: E96; U/M: EA; AEC Category: Q200; Green_Lifecycle: Active; Green_REACh: Passed
R242 R243 = ERJ-6GEYJ335V: RES, 3.3 M, 5%, 0.125 W, 0805; Manufacturer: Panasonic; CompType: Resistor; Value: 3.3Meg; Res_ohm: 3300000; Value_Code: 3M30; Tolerance_%: 5; Power_W: 0.125; Value2: 0.125W; VDC_V: 150; TempCo: 150 ppm/C; SizeArea_mm2: 2.5; SizeX_mm: 2; SizeY_mm: 1.25; SizeZ_mm: 1.45; EIA_Code: E24; U/M: EA; AEC Category: Q200
R244-R246 = PR02000201003JR500: RES, 100 k, 5%, 2 W, AEC-Q200 Grade 0, Axial resistor; Manufacturer: Vishay-Bccomponents; Value: 100k; Res_ohm: 100000; Tolerance_%: 5; Power_W: 2; Value2: 2W; VDC_V: 500; TempCo: 250 ppm/C; EIA_Code: E24; U/M: EA; AEC Category: Q200; AEC Qualified: Y; AEC Grade: 0
R250 = CRCW08054K70JNEA: RES, 4.7 k, 5%, 0.125 W, 0805; Manufacturer: Vishay-Dale; CompType: Resistor; Value: 4.7k; Res_ohm: 4700; Value_Code: 4k70; Tolerance_%: 5; Power_W: 0.125; Value2: 0.125W; VDC_V: 150; TempCo: 200 ppm/C; SizeArea_mm2: 2.5; SizeX_mm: 2; SizeY_mm: 1.25; SizeZ_mm: 1.45; EIA_Code: E24; U/M: EA; AEC Category: Q200; Green_Lifecycle: Active; Green_REACh: Passed
R251 = CRCW080520K0JNEA: RES, 20 k, 5%, 0.125 W, 0805; Manufacturer: Vishay-Dale; CompType: Resistor; Value: 20k; Res_ohm: 20000; Value_Code: 20k0; Tolerance_%: 5; Power_W: 0.125; Value2: 0.125W; VDC_V: 150; TempCo: 200 ppm/C; SizeArea_mm2: 2.5; SizeX_mm: 2; SizeY_mm: 1.25; SizeZ_mm: 1.45; EIA_Code: E24; U/M: EA; AEC Category: Q200; Green_Lifecycle: Active; Green_REACh: Passed
T100 = EE42: Transformer, 400uH, 14-pin, TH, EE49; Manufacturer: Jewel; SymbolVersion: Rev03; SymbolCreator: Altium
TP200 TP202 TP204 TP206 = 5011: Test Point, Multipurpose, Black, TH; Manufacturer: Keystone; CompType: Test Point Loop; U/M: EA
TP201 TP203 TP205 = 5010: Test Point, Multipurpose, Red, TH; Manufacturer: Keystone; CompType: Test Point Loop; U/M: EA
U200 = CMP-0077203-3: Wide Vin LLC Resonant Controller With High-Voltage Start Up Enabling Low Standby Power, DDB0014A (SOIC-14); Alternate PartNumber: UCC25640-4DDBT; Alternate Manufacturer: Texas Instruments; SizeAreaWB_mm2: 95.2; SizeZ_mm: 1.75; SizeX_mm: 6.0; SizeY_mm: 9.9; SizeArea_mm2: 59.4; CompType: IC; AEC Qualified: N; AEC Category: Q200
U201 U202 = VO618A: Optocoupler, 5.3 kV, 50-600% CTR, TH; Manufacturer: Vishay-Semiconductor; CTR (Min): 50%; CTR (Max): 600%; Voltage_Isolation_Vrms: 5300V; SizeAreaWB_mm2: 71.064; SizeArea_mm2: 40.304; SizeX_mm: 8.8; SizeY_mm: 4.58; SizeZ_mm: 5
U203 = TL431AIDBZR: Adjustable Precision Shunt Regulator, 34 ppm / degC, 100 mA, -40 to 85 degC, 3-pin SOT-23 (DBZ), Green (RoHS & no Sb/Br); Manufacturer: Texas Instruments; Alternate PartNumber: Equivalent; Initial Accuracy @ 25/deg C(%): 1; Iout/Iz(Max)(mA): 100; Min Iz for Regulation(uA): 600; Rating: Catalog; SubFamily: Shunt Voltage Reference; Temp Coeff(Max)(ppm/ degree C): 92; Temp Coeff(Typ)(ppm/ degree C): 34; VO Adj(Max)(V): 36; VO Adj(Min)(V): 2.495

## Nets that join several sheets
PGND: PMP40580_PFC (28 pins), PMP40580_LLC (48 pins)
SGND: PMP40580_PFC (8 pins), PMP40580_LLC (39 pins)
ACIN: PMP40580_PFC (5 pins), PMP40580_LLC (R222.2)
HV: PMP40580_PFC (R102.1), PMP40580_LLC (U200.1)
PFC_DC+: PMP40580_PFC (7 pins), PMP40580_LLC (C200.2 C201.2 C203.1 Q200.2)
PFC_VCC: PMP40580_PFC (R112.2), PMP40580_LLC (J205.1 J205.2 Q202.2 R207.2)

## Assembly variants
001: not fitted C106 C107 C114 C201 C202 C209 D204 D214 FID1 FID2 FID3 H9 H10 H11 H12 Q202 Q203 R208 R209 R210 R238 R239; alternate parts C108 -> 450MPK105J
002: not fitted C106 C107 C114 C201 C202 C209 C210 C221 C231 C233 D204 D206 D214 FID1 FID2 FID3 H9 H10 H11 H12 J206 Q202 Q203 Q204 Q205 Q206 R208 R209 R210 R211 R212 R214 R226 R227 R228 R229 R232 R238 R239 R242 R243 R246 U201; alternate parts C108 -> 450MPK105J, C215 -> GRM21BZ71E106KE15L, C214 -> GRM21BZ71E106KE15L, C206 -> VJ1206A470JXGAT5Z, C207 -> GRM3195C1H472JA01D, R216 -> CRCW0805220KJNEA, R217 -> CRCW0805120KJNEA, C232 -> C0805C104J5RACTU, R233 -> CRCW080515K0JNEA, R235 -> ERJ-6GEY0R00V, R230 -> CRCW08056K04FKEA, R231 -> CRCW080510K0JNEA, R225 -> CRCW0805180KJNEA, R236 -> CRCW080522R0JNEA, U203 -> TLVH432AIDBZR, R248 -> CRCW0805100KJNEA, R249 -> CRCW0805100KJNEA, Q208 -> SI2309CDS-T1-E3, C220 -> 08053C224JAT2A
